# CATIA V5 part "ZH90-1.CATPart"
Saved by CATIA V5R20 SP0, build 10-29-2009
Part number: ZH901
Bounding box of the stored display mesh (mm): x 0 to 152, y -15.5 to 44.5, z -29.7 to 15
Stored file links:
  C:\Users\Utente\Desktop\IO LAVORO\3D X SITO CF\X SITO\PLASTICA\ZH90\ZH90-1.CATPart
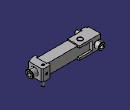
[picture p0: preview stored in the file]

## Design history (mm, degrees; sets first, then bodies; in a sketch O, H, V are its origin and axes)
Set1
  DatumSurface1 to DatumSurface20 "_ZH90/1_head"
  DatumSurface21 to DatumSurface38 "_ZH90/1_screw1"
  DatumSurface39 to DatumSurface56 "_ZH90/1_hand"
  DatumSurface57 to DatumSurface74 "_ZH90/1_screw2"
  DatumSurface75 to DatumSurface95 "_ZH90/1_he"
  DatumSurface96 to DatumSurface110 "_ZH90/1_screw3"
  DatumSurface111 to DatumSurface118 "_ZH90/1_stift1"
  DatumSurface119 to DatumSurface128 "_ZH90/1_stift2"
Body1 (main body)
